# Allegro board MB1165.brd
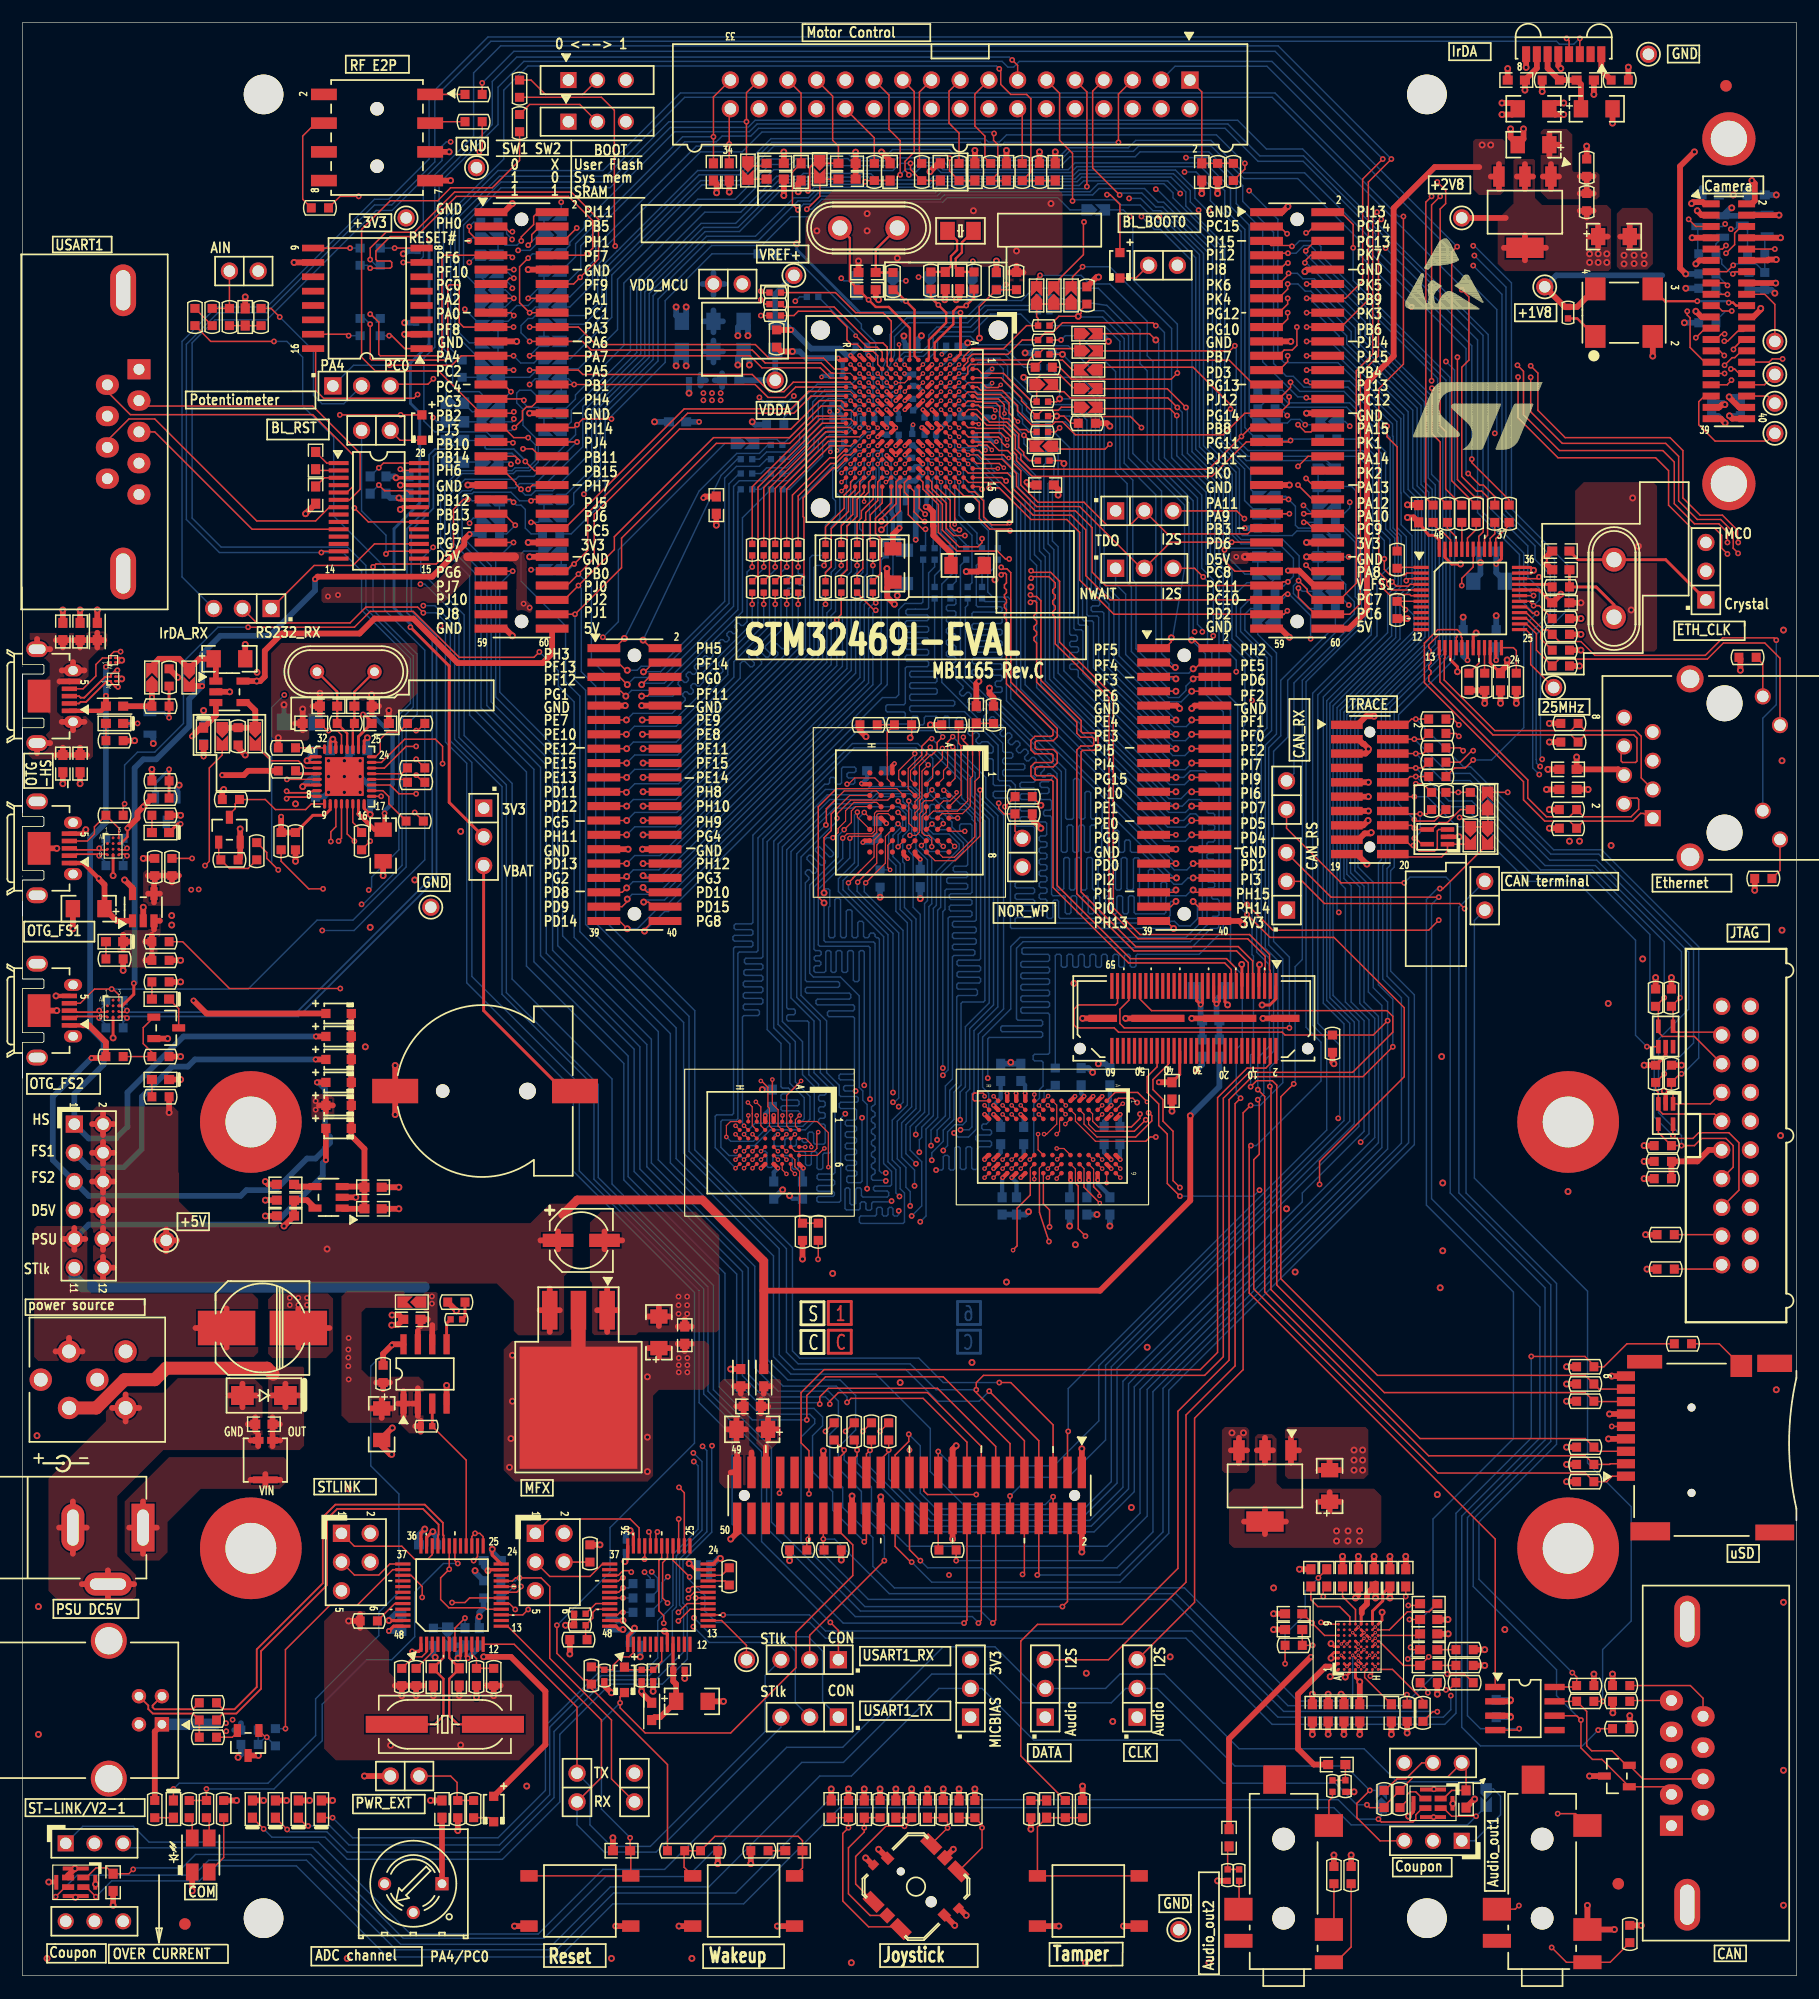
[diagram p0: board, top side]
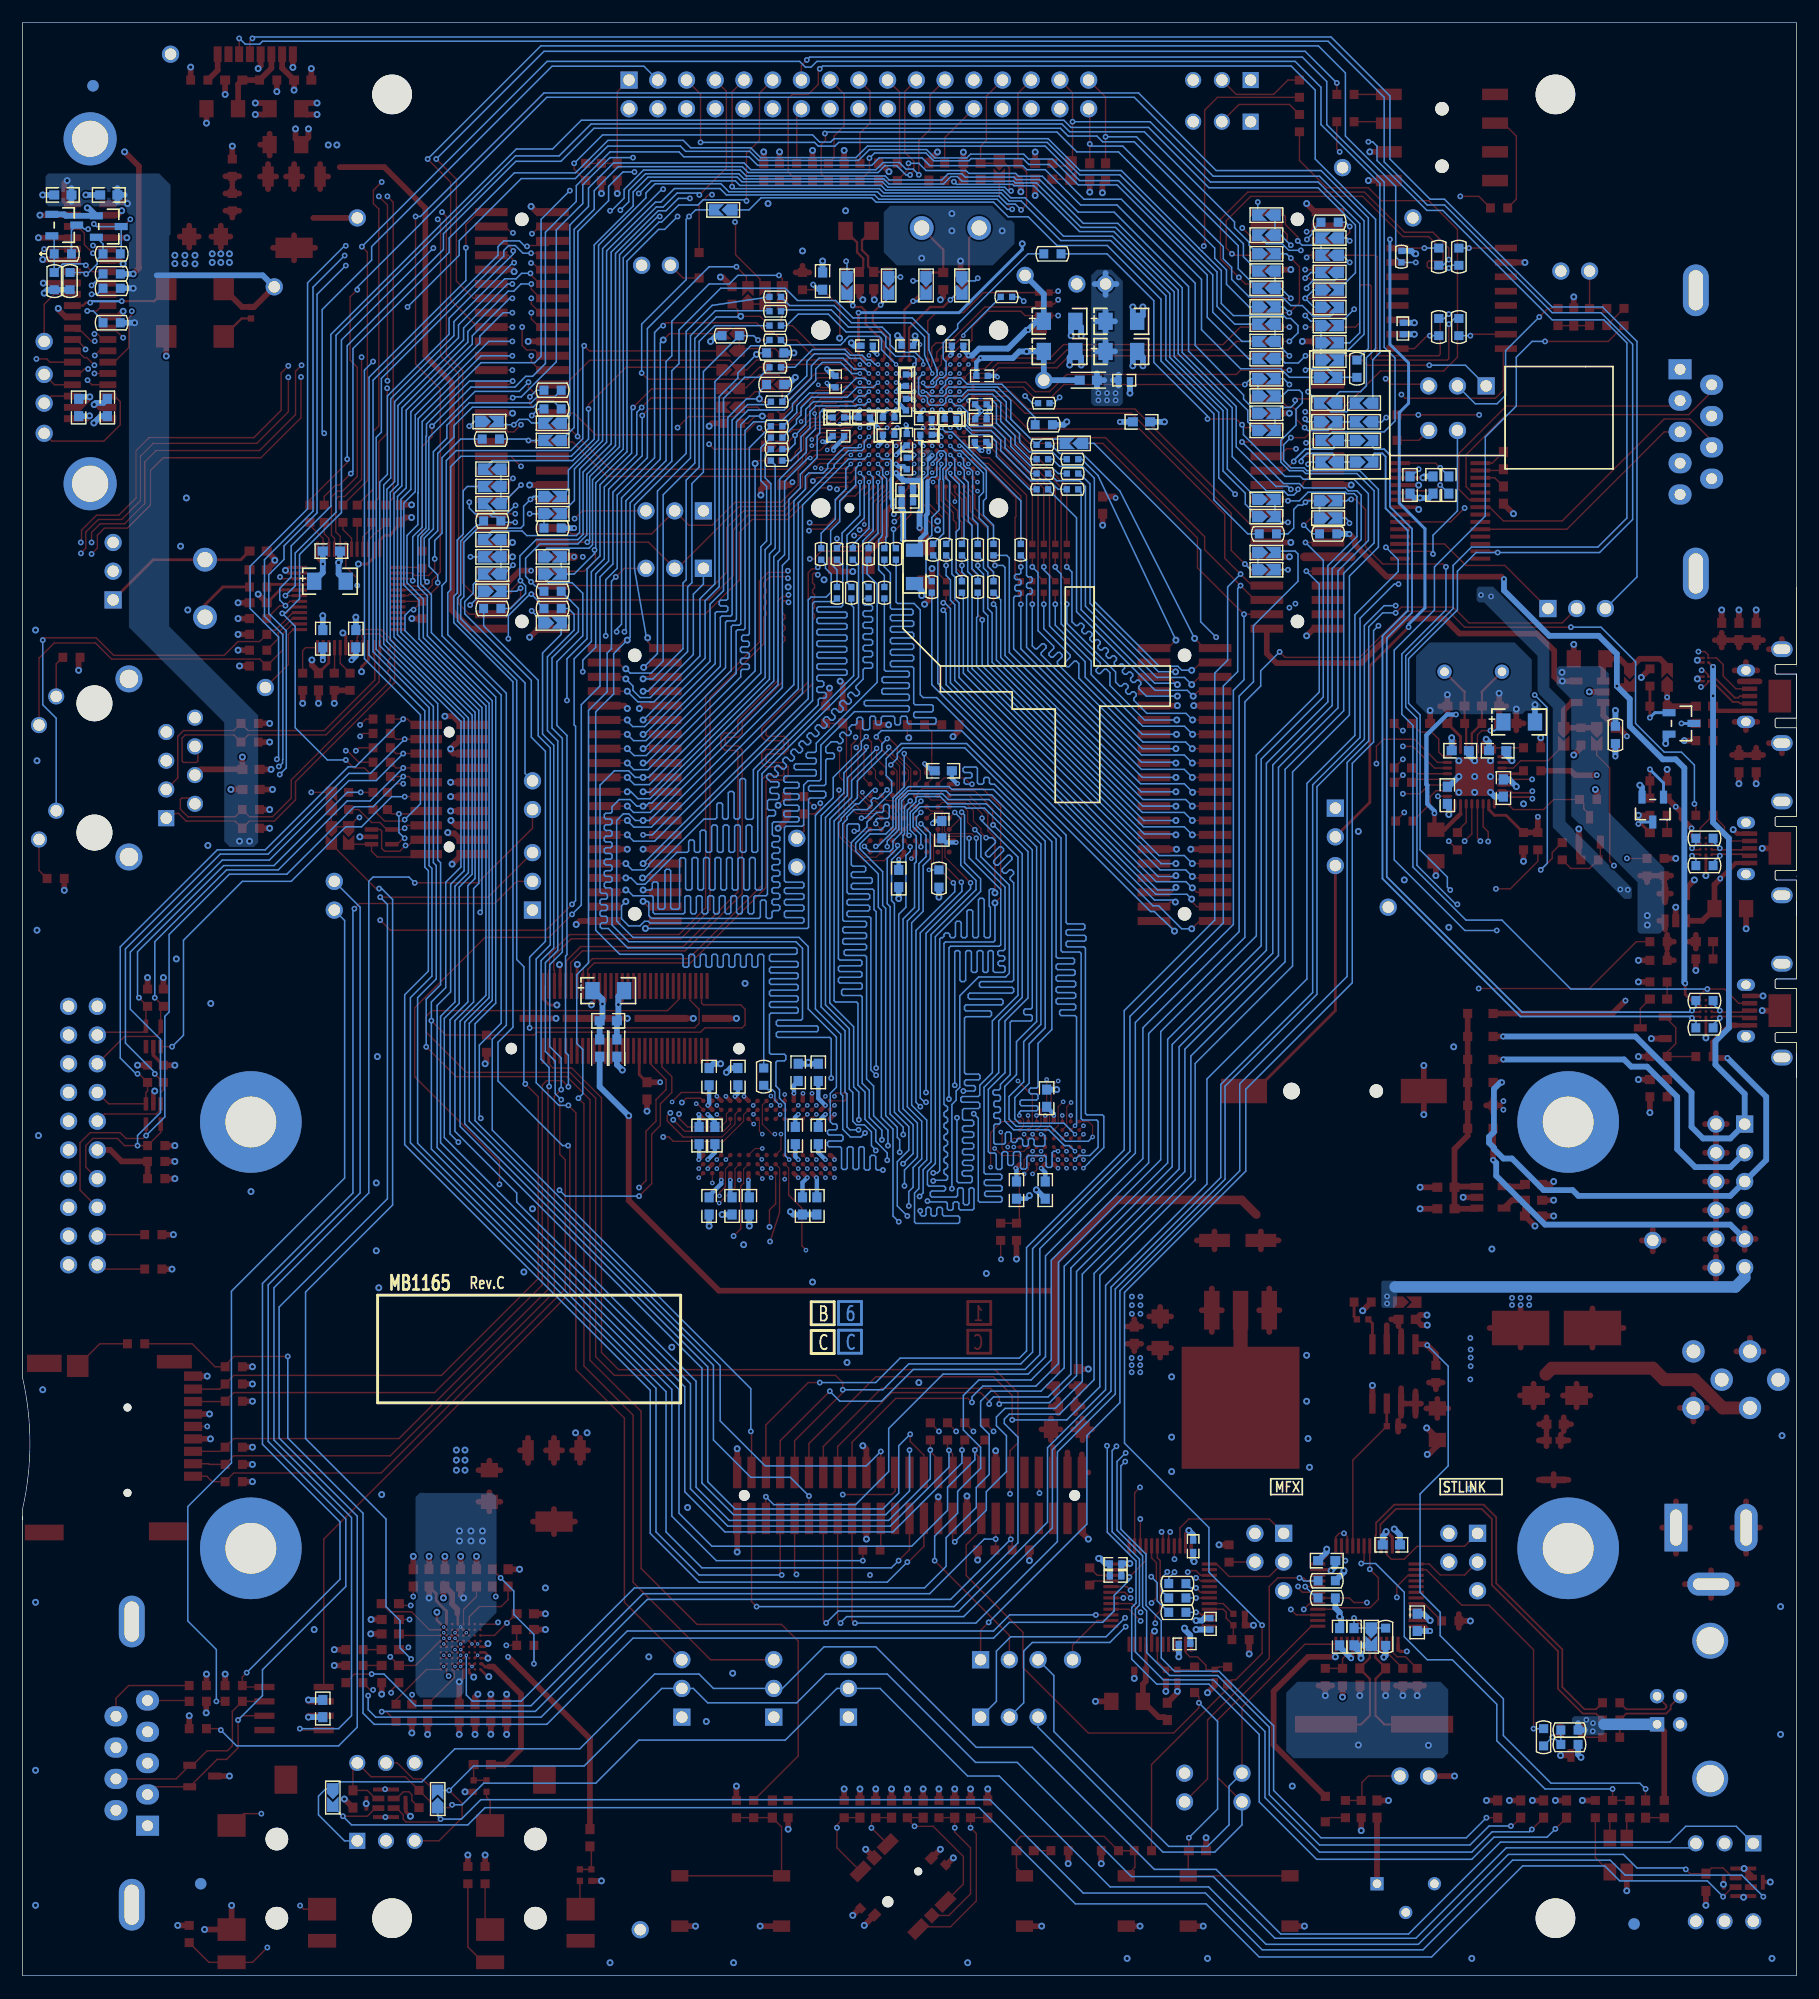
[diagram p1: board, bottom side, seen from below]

Outline 156.84 x 172.72 mm; copper layers: TOP, L2_GND, L3_SIG, L4_VCC, L5_GND, BOTTOM. Coordinates in mm from the lower left corner of the outline.
Outline path: 0,115.82 0,115.8 ; 0,115.14 0,102.87 ; 0,97.26 0,97.21 ; 0,172.72 156.84,172.72 156.84,52.86 arc(156.2,47.08) 156.84,41.3 156.84,40.28 156.84,40.59 156.84,0 0,0 0,81.53 0,79.38 0,82.54 1.79,82.54 1.89,82.64 1.89,83.29 1.79,83.39 0,83.39 0,87.29 1.79,87.29 1.89,87.39 1.89,88.04 1.79,88.14 0,88.14 0,95 0,93.73 0,96.89 1.79,96.89 1.89,96.99 1.89,97.64 1.79,97.75 0,97.75 0,101.64 1.79,101.64 1.89,101.75 1.89,102.4 1.79,102.5 0,102.5 0,109.35 0,107.19 0,110.36 1.79,110.36 1.89,110.46 1.89,111.11 1.79,111.21 0,111.21 0,115.11 1.79,115.11 1.89,115.21 1.89,115.86 1.79,115.96 0,115.96 0,172.72

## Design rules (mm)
net group +2V8: nets I2C1_SCL_C I2C1_SDA_C
net group +3V3_ST_LINK: nets NETLD12_4 STM_RST
net group A0: nets A0 NETR236_1
net group A1: nets A1 NETR232_1
net group A2: nets A2 NETR230_1
net group A3: nets A3 NETR226_1
net group A4: nets A4 NETR223_1
net group A5: nets A5 NETR221_1
net group A6: nets A6 NETR248_1
net group A7: nets A7 NETR245_1
net group A8: nets A8 NETR249_1
net group A9: nets A9 NETR261_1
net group A10: nets A10 NETR251_1
net group A11: nets A11 NETR250_1
net group A12: nets A12 NETR269_1
net group A13: nets A13 NETR257_1
net group A14: nets A14 NETR270_1
net group A15: nets A15 NETR259_1
net group A16: nets A16 NETR260_2
net group A17: nets A17 NETR271_1
net group A18: nets A18 NETR258_1
net group BOOT0: nets BOOT0 NETR3_2
net group D0: nets D0 NETR268_1
net group D1: nets D1 NETR256_1
net group D2: nets D2 NETR262_1
net group D3: nets D3 NETR273_1
net group D4: nets D4 NETR58_1
net group D5: nets D5 NETR50_1
net group D6: nets D6 NETR49_1
net group D7: nets D7 NETR59_1
net group D8: nets D8 NETR51_1
net group D9: nets D9 NETR60_1
net group D10: nets D10 NETR62_1
net group D11: nets D11 NETR52_1
net group D12: nets D12 NETR61_1
net group D13: nets D13 NETR56_1
net group D14: nets D14 NETR65_1
net group D15: nets D15 NETR66_1
net group D16: nets D16 NETR53_2
net group D17: nets D17 NETR54_2
net group D18: nets D18 NETR63_2
net group D19: nets D19 NETR64_2
net group D20: nets D20 NETR55_2
net group D21: nets D21 NETR266_2
net group D22: nets D22 NETR276_2
net group D23: nets D23 NETR275_2
net group D24: nets D24 NETR265_2
net group D25: nets D25 NETR264_2
net group D26: nets D26 NETR263_2
net group D27: nets D27 NETR274_2
net group D28: nets D28 NETR247_2
net group D29: nets D29 NETR240_2
net group D30: nets D30 NETR241_2
net group D31: nets D31 NETR244_2
net group DIFFPAIR1: nets NETCN9_2 NETCN9_3
net group LCD_B4: nets LCD_B4 NETLD1_2
net group LCD_B5: nets LCD_B5 NETLD2_2
net group LCD_B6: nets LCD_B6 NETLD3_2
net group LCD_B7: nets LCD_B7 NETLD4_2
net group MIC_CLK: nets MIC_CLK NETSB25_2
net group MIC_DATA: nets MIC_DATA NETSB26_1
net group NETC11_1: nets NETC11_1 NETCN1_26
net group NETC12_2: nets NETC12_2 NETCN1_19
net group NETC13_2: nets NETC13_2 NETCN1_17
net group NETC14_2: nets NETC14_2 NETCN1_15
net group NETC15_1: nets NETC15_1 NETCN1_14
net group NETC16_2: nets NETC16_2 PA6
net group NETC20_1: nets NETC20_1 PH0
net group NETC21_1: nets NETC21_1 PC15
net group NETC22_1: nets NETC22_1 PC14
net group NETC25_1: nets NETC25_1 NETC25_2
net group NETC33_2: nets NETC33_2 NETR67_1
net group NETC39_1: nets NETC39_1 NETC40_1
net group NETC75_1: nets NETC75_1 NETC75_2
net group NETC80_1: nets NETC80_1 NETC80_2
net group NETC81_1: nets NETC81_1 NETC81_2
net group NETC139_1: nets NETC139_1 NETC139_2
net group NETC155_1: nets NETC155_1 NETC155_2
net group NETCN4_31: nets NETCN4_31 PA4
net group NETCN12_2: nets NETCN12_2 PA13
net group NETCN12_4: nets NETCN12_4 PA14
net group NETCN12_8: nets NETCN12_8 PA15
net group NETCN13_2: nets NETCN13_2 PA11
net group NETCN13_4: nets NETCN13_4 PA10
net group NETCN17_2: nets NETCN17_2 PAR_D4
net group NETCN17_3: nets NETCN17_3 PAR_D11
net group NETCN17_7: nets NETCN17_7 PAR_D2
net group NETCN17_8: nets NETCN17_8 PAR_D3
net group NETCN17_10: nets NETCN17_10 NETR142_1
net group NETCN18_22: nets NETCN18_22 PK7
net group NETCN22_3: nets NETCN22_3 NETR182_2
net group NETCN23_7: nets NETCN23_7 NETJP13_1
net group NETD15_2: nets NETD15_2 NETJP20_2
net group NETJP7_3: nets NETJP7_3 PA8
net group NETJP18_3: nets NETJP18_3 PAR_D1
net group NETLD6_2: nets NETLD6_2 NETR111_1
net group NETR6_1: nets NETR6_1 PB2
net group NETR40_1: nets NETR40_1 PB6
net group NETR41_1: nets NETR41_1 PG15
net group NETR42_1: nets NETR42_1 PH7
net group NETR48_1: nets NETR48_1 PF11
net group NETR69_1: nets NETR69_1 PA2
net group NETR82_1: nets NETR82_1 PA3
net group NETR84_1: nets NETR84_1 PD7
net group NETR88_2: nets NETR88_2 NETSB16_1
net group NETR94_1: nets NETR94_1 PB10
net group NETR98_1: nets NETR98_1 PB11
net group NETR99_1: nets NETR99_1 PD5
net group NETR113_1: nets NETR113_1 PA5
net group NETR134_1: nets NETR134_1 PG9
net group NETR140_1: nets NETR140_1 NETR140_2
net group NETR214_2: nets NETR214_2 PI14
net group NETR222_1: nets NETR222_1 PF10
net group NETR233_2: nets NETR233_2 PC2
net group NETR235_2: nets NETR235_2 PG14
net group NETR242_2: nets NETR242_2 PG11
net group NETR243_2: nets NETR243_2 PH3
net group NETR246_2: nets NETR246_2 PH5
net group NETR267_1: nets NETR267_1 PG8
net group NETR285_1: nets NETR285_1 PH2
net group NETR290_2: nets NETR290_2 PI8
net group NETSB31_2: nets NETSB31_2 PC1
net group NETSB32_2: nets NETSB32_2 PI11
net group NETSB34_2: nets NETSB34_2 PC0
net group NETSB56_2: nets NETSB56_2 PH4
net group PB0: nets PB0 ULPI_D1
net group PB1: nets PB1 ULPI_D2
net group PB5: nets PB5 ULPI_D7
net group VDDA: nets VDDA VREF+
net group +1V8: nets NETR26_1
net group +5V: nets NETLD10_1
net group A19: nets A19 NETCN12_6 NETCN12_14 NETR37_1 NETSB9_1 T_JTDO
net group A20: nets A20 NETCN12_16 NETCN16_3 NETR35_1 NETSB7_1 PB4
net group A21: nets A21 NETCN12_18 NETR32_1 NETSB5_1 PAR_D6
net group A22: nets A22 NETCN12_20 NETR34_1 NETSB19_1 PAR_D7
net group A23: nets A23 NETCN12_12 NETR38_1 NETR238_1
net group DATA: nets NETR289_2 PE0 PE1 PI4 PI5
net group LCD_R0: nets LCD_R0 MII_TXD0 NETR254_1 PB12 PG13 ULPI_D5
net group LED_STLINK: nets LED_STLINK NETLD12_2 NETLD12_3
net group MIC_VDD: nets MIC_VDD NETCN25_5 NETR186_1
net group NETB2_2: nets NETB2_2 NETR163_1 NETR163_2 PA0
net group NETB3_2: nets NETB3_2 NETC100_1 PC13
net group NETC24_2: nets NETC24_2 NETCN3_1 NETJP3_2 NETR28_1 NETR28_2
net group NETC37_1: nets NETC37_1 NETL2_1 NETR74_2 NETR95_1
net group NETC69_1: nets NETC69_1 NETC69_2 NETC78_2
net group NETC92_1: nets NETC92_1 NETC92_2 NETCN26_6
net group NETC101_1: nets NETC101_1 NETC101_2 NETCN26_4
net group NETCN2_1: nets NETCN2_1 NETR172_2 NETR288_2 PB9
net group NETCN2_3: nets NETCN2_3 NETR179_2 NETR287_2 PB8
net group NETCN12_10: nets NETCN5_5 NETCN12_10 NETR114_1 RESET#
net group NETCN13_3: nets NETCN13_3 NETD5_C3 NETSB67_1 PA12
net group NETCN14_2: nets NETCN14_2 NETD6_D3 PB14
net group NETCN14_3: nets NETCN14_3 NETD6_C3 PB15
net group NETCN17_1: nets NETCN2_4 NETCN17_1 PAR_D8
net group NETCN22_2: nets NETCN22_2
net group NETJP19_2: nets NETJP19_2 NETR97_2 PA9 VBUS_FS1
net group NETLD8_2: nets NETR119_1
net group NETLD11_1: nets NETLD11_1 NETLD11_2 NETR292_1 PWR_ENN USB_RENUMN VUSB_ST_LINK
net group NETR43_1: nets NETR43_1 NETR43_2 PH6
net group NETR44_1: nets NETR44_1 NETR44_2 PC5
net group NETR45_1: nets NETR45_1 NETR45_2 PC4
net group NETR46_1: nets NETR46_1 NETR46_2 PA7
net group NETR47_1: nets NETR47_1 NETR47_2 PA1
net group NETR57_1: nets NETR57_1 NETR57_2 PC3
net group NETR109_1: nets NETR109_1 NETR126_2 PB13 VBUS_FS2
net group NETR116_2: nets NETR117_2
net group NETR216_1: nets NETR27_1 NETR216_1 PF9
net group NETR217_2: nets NETR23_1 NETR217_2 PF7
net group NETR227_1: nets NETR25_1 NETR227_1 PF6
net group NETR228_2: nets NETR228_2 NETR237_1 PF8

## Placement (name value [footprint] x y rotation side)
B1  TD-0341 [RESET_Black]  [PB10]  49.28 6.6 0 top
B2  WKUP  [PB10]  63.75 6.6 0 top
B3  USER (Blue)  [PB10]  94.23 6.6 0 top
B4  EVQQ7  [SW-JOY]  78.99 7.87 45 top
BT1  CR1220 holder  [BAT_2SM_CR1220]  40.89 78.23 180 top
C1  100nF  [0603C]  132.08 167.64 180 top
C2  100nF  [0603C]  138.18 167.64 0 top
C3  4.7uF  [TAN-A]  133.6 165.1 0 top
C4  4.7uF  [TAN-A]  139.19 165.1 180 top
C5  10uF  [TAN-A]  133.6 161.93 0 top
C6  [N_A]  [0603C]  66.55 160.27 180 top
C7  [N_A]  [0603C]  72.9 160.27 180 top
C8  [N_A]  [0603C]  61.09 159.51 90 top
C9  [N_A]  [0603C]  62.48 159.51 90 top
C10  [N_A]  [0603C]  68.83 159.51 90 top
C11  100nF  [0603C]  76.71 159.51 90 top
C12  [N_A]  [0603C]  81.15 159.51 270 top
C13  [N_A]  [0603C]  84.2 159.51 270 top
C14  [N_A]  [0603C]  87 159.51 270 top
C15  100nF  [0603C]  91.31 159.51 90 top
C16  1nF  [0603C]  104.27 159.51 90 top
C17  10nF  [0603C]  66.55 158.88 0 top
C18  [N_A]  [0603C]  72.9 158.88 180 top
C19  10uF  [TAN-A]  140.72 153.8 180 top
C20  20pF  [0603C]  74.68 150.62 180 top
C21  1.5pF  [0603C]  81.58 149.91 270 top
C22  1.5pF  [0603C]  82.85 149.91 270 top
C23  20pF  [0603C]  74.68 149.1 0 top
C24  [N_A]  [0603C]  19.68 146.69 270 top
C25  100nF  [0603C]  25.91 133.99 270 top
C26  [N_A]  [0603C]  90.42 131.83 180 top
C27  100nF  [0603C]  25.91 130.94 90 top
C28  [N_A]  [0603C]  61.34 130.05 90 top
C29  100nF  [0603C]  123.44 129.29 90 top
C30  22pF  [0603C]  136.02 125.98 180 top
C31  2.2uF[N_A]  [1206C]  76.96 124.71 270 top
C32  2.2uF  [1206C]  83.57 124.71 0 top
C33  22pF  [0603C]  136.02 124.33 0 top
C34  100nF  [0603C]  136.02 121.41 180 top
C35  100nF  [0603C]  3.56 118.87 90 top
C36  100nF  [0603C]  5.08 118.87 90 top
C37  4.7uF  [TAN-A]  18.29 116.46 180 top
C38  100nF  [0603C]  130.68 114.43 90 top
C39  33pF  [0603C]  27.05 112.27 180 top
C40  33pF  [0603C]  30.1 112.27 0 top
C41  100nF  [0603C]  84.33 111.51 90 top
C42  100nF  [0603C]  25.53 110.74 180 top
C43  100nF  [0603C]  31.62 110.74 0 top
C44  100nF  [0603C]  3.56 107.19 270 top
C45  100nF  [0603C]  5.08 107.19 270 top
C46  100nF  [0603C]  136.65 106.68 0 top
C47  100nF  [0603C]  136.65 104.9 0 top
C48  4.7uF  [TAN-A]  31.88 99.95 90 top
C49  4.7uF  [TAN-A]  5.84 94.36 0 top
C52  100nF  [0603C]  101.63 78.24 270 top
C53  10nF_X7R_0603  [0603C]  23.24 69.98 0 top
C54  1uF_X5R_0603  [0603C]  30.99 69.72 180 top
C55  100nF  [0603C]  23.24 68.58 0 top
C56  100nF  [0603C]  30.99 67.82 180 top
C57  1uF_X5R_0603  [0603C]  23.24 67.18 180 top
C58  47uF  [CAE_5R3X5R3_H5R4]  49.4 65.02 0 top
C59  100nF  [0603C]  34.42 58.04 0 top
C60  220uF  [C310M-6]  21.21 57.28 180 top
C61  10uF  [TAN-A]  56.26 56.9 270 top
C62  100nF  [0603C]  58.55 56.64 90 top
C63  100nF  [0603C]  64.52 50.34 180 top
C64  100nF  [0603C]  21.34 48.77 180 top
C65  4.7uF  [TAN-A]  31.75 48.77 90 top
C66  10uF  [TAN-A]  64.52 48.31 0 top
C67  10uF  [TAN-A]  115.57 43.31 270 top
C68  4.7uF  [0603C]  113.92 35.18 270 top
C69  1uF  [0603C]  115.32 35.18 90 top
C70  4.7uF  [0603C]  116.71 35.18 90 top
C71  4.7uF  [0603C]  118.11 35.18 90 top
C72  1uF  [0603C]  119.51 35.18 90 top
C73  100nF  [0603C]  120.9 35.18 90 top
C74  1uF  [0603C]  122.3 35.18 90 top
C75  2.2uF  [0603C]  124.33 32.89 180 top
C76  4.7uF  [0603C]  112.39 32 0 top
C77  2.2uF  [0603C]  124.33 31.5 0 top
C78  4.7uF  [0603C]  112.39 30.61 0 top
C79  2.2uF  [0603C]  124.33 30.23 0 top
C80  100nF  [0603C]  124.33 28.83 0 top
C81  100nF  [0603C]  124.33 27.43 0 top
C82  100nF  [0402C]  58.04 27.05 180 top
C83  100nF[N_A]  [0402C]  55.75 26.54 90 top
C84  20pF  [0603C]  36.32 26.42 270 top
C85  20pF  [0603C]  38.61 26.42 270 top
C86  1uF  [TAN-A]  59.18 24.26 180 top
C87  100nF  [0603C]  114.05 23.24 270 top
C88  100nF  [0603C]  115.44 23.24 270 top
C89  4.7uF  [0603C]  116.84 23.24 270 top
C90  100nF  [0603C]  118.24 23.24 270 top
C91  1uF  [0603C]  121.03 23.24 270 top
C92  4.7uF  [0603C]  116.2 18.67 180 top
C93  100nF  [0603C]  127.64 15.62 270 top
C94  100nF  [0603C]  37.08 14.73 90 top
C95  10nF[N_A]  [0603C]  71.5 14.73 270 top
C96  10nF[N_A]  [0603C]  74.42 14.73 270 top
C97  10nF[N_A]  [0603C]  77.22 14.73 270 top
C98  10nF[N_A]  [0603C]  80.01 14.73 270 top
C99  10nF[N_A]  [0603C]  82.8 14.73 270 top
C100  100nF  [0603C]  90.55 14.73 270 top
C101  4.7uF  [0603C]  106.68 12.19 90 top
C102  100nF  [0603C]  52.96 11.05 0 top
C103  [N_A]  [0603C]  68.2 11.05 0 top
C104  100nF  [0603C]  8 8.26 270 top
C105  100nF  [0603C]  153.29 157.48 0 bottom
C106  100nF  [0603C]  149.22 157.48 180 bottom
C107  [N_A]  [0603C]  86.11 149.86 270 bottom
C108  1uF  [TAN-A]  65.15 146.3 0 bottom
C109  4.7uF  [TAN-A]  59.69 146.3 0 bottom
C110  100nF  [0402C]  34.8 145.67 90 bottom
C111  100nF  [0402C]  82.17 144.15 0 bottom
C112  100nF  [0402C]  78.61 144.15 0 bottom
C113  100nF  [0402C]  74.17 144.15 180 bottom
C114  1uF  [TAN-A]  65.15 143.64 0 bottom
C115  4.7uF  [TAN-A]  59.69 143.64 0 bottom
C116  100nF  [0402C]  72.01 141.48 0 bottom
C117  100nF  [0402C]  78.74 141.1 90 bottom
C118  100nF  [0402C]  59.44 141.1 180 bottom
C119  100nF  [0402C]  84.96 140.97 90 bottom
C120  100nF  [0402C]  72.11 138.96 180 bottom
C121  100nF  [0402C]  78.74 138.94 270 bottom
C122  100nF  [0603C]  151.89 138.68 90 bottom
C123  100nF  [0603C]  149.35 138.68 90 bottom
C124  100nF  [0402C]  84.71 137.79 180 bottom
C125  100nF  [0402C]  82.42 137.79 0 bottom
C126  100nF  [0402C]  80.26 137.79 180 bottom
C127  100nF  [0402C]  76.96 137.67 0 bottom
C128  100nF  [0402C]  74.8 137.67 180 bottom
C129  100nF  [0402C]  72.11 137.64 180 bottom
C130  [N_A]  [0603C]  57.91 137.41 0 bottom
C131  100nF  [0402C]  80.26 136.27 180 bottom
C132  100nF  [0402C]  76.96 136.27 0 bottom
C133  100nF  [0402C]  84.71 136.14 180 bottom
C134  100nF  [0402C]  78.66 135.84 90 bottom
C135  100nF  [0402C]  72.14 135.64 180 bottom
C136  100nF  [0402C]  78.66 133.73 270 bottom
C137  100nF  [0603C]  34.16 131.83 90 bottom
C138  100nF  [0603C]  32.13 131.83 270 bottom
C139  100nF  [0603C]  30.73 131.83 90 bottom
C140  2.2uF  [0402C]  78.61 131.44 0 bottom
C141  100nF  [0402C]  78.61 130.3 0 bottom
C142  100nF  [0603C]  129.54 125.98 0 bottom
C143  2.2uF  [1206C]  77.98 124.59 270 bottom
C144  10uF  [TAN-A]  129.67 123.32 0 bottom
C145  100nF  [0603C]  130.3 118.24 90 bottom
C146  100nF  [0603C]  127.38 118.24 270 bottom
C147  4.7uF  [TAN-A]  24.51 110.87 0 bottom
C148  100nF  [0603C]  29.72 108.33 180 bottom
C149  100nF  [0603C]  26.42 108.33 180 bottom
C150  100nF  [0603C]  75.44 106.55 180 bottom
C151  100nF  [0603C]  25.91 105.03 270 bottom
C152  100nF  [0603C]  30.86 104.39 90 bottom
C153  100nF  [0603C]  75.56 101.35 270 bottom
C154  100nF  [0603C]  79.38 97.03 270 bottom
C155  10uF  [TAN-A]  105.06 87.11 0 bottom
C156  100nF  [0603C]  105.06 84.44 180 bottom
C157  100nF  [0603C]  88.27 79.88 90 bottom
C158  100nF  [0603C]  86.49 79.88 90 bottom
C159  100nF  [0603C]  96.14 79.5 90 bottom
C160  100nF  [0603C]  93.6 79.5 90 bottom
C161  100nF  [0603C]  66.29 77.6 90 bottom
C162  100nF  [0603C]  97.03 74.3 90 bottom
C163  100nF  [0603C]  95.63 74.3 90 bottom
C164  100nF  [0603C]  88.52 74.3 90 bottom
C165  100nF  [0603C]  86.49 74.3 90 bottom
C166  100nF  [0603C]  68.96 69.47 270 bottom
C167  100nF  [0603C]  66.42 69.47 270 bottom
C168  100nF  [0603C]  96.14 68.07 270 bottom
C169  100nF  [0603C]  94.11 68.07 270 bottom
C170  100nF  [0603C]  92.58 68.07 270 bottom
C171  100nF  [0603C]  87.88 68.07 270 bottom
C172  100nF  [0603C]  86.61 68.07 270 bottom
C173  100nF  [0603C]  35.81 38.1 180 bottom
C174  100nF  [0402C]  53.34 37.97 270 bottom
C175  100nF  [0603C]  41.53 36.7 0 bottom
C176  100nF  [0402C]  60.2 36.45 180 bottom
C177  100nF  [0402C]  60.2 35.31 0 bottom
C178  100nF  [0603C]  33.53 31.24 270 bottom
C179  100nF  [0402C]  51.82 31.11 270 bottom
C180  100nF  [0603C]  40.39 29.97 270 bottom
C181  100nF  [0603C]  39.12 29.97 90 bottom
C182  100nF  [0402C]  54.1 29.34 180 bottom
C183  100nF  [0603C]  130.3 23.62 90 bottom
CN1  MC_connector  [IDC34S]  103.22 167.64 270 top
CN2  F206A-2_04MGF-A  [SSM-104-L-DH]  31.34 162.56 90 top
CN3  -  [SIP2]  18.29 150.75 0 top
CN4  F1000-2_20MGF-L0A  [CLM-120-02-L-D]  150.88 147.19 270 top
CN5  P1039-2_30MGF-089-1A  [FTR-130-53-L-D-LC]  44.12 137.54 270 top
CN6  P1039-2_30MGF-089-1A  [FTR-130-53-L-D-LC]  112.7 137.54 270 top
CN7  DB9-male USART1  [DB9_M]  10.29 136.53 90 top
CN8  475900001  [MOLEX_47590001]  4.14 113.16 270 top
CN9  J0011D21B  [RJ45_J0011D01BNL]  144.15 102.36 270 top
CN10  P1039-2_20MGF-089-1A  [FTR-120-53-L-D-LC]  54.1 105.33 270 top
CN11  P1039-2_20MGF-089-1A  [FTR-120-53-L-D-LC]  102.72 105.33 270 top
CN12  P127B-2_10MGF-079-1E7A  [FTSH-110-01-L-DV]  119.13 104.9 270 top
CN13  475900001  [MOLEX_47590001]  4.14 99.69 270 top
CN14  475900001  [MOLEX_47590001]  4.14 85.34 270 top
CN15  -  [QSH-030-01-F-D-A]  103.57 84.66 180 top
CN16  JTAG  [IDC20S]  150.24 85.72 0 top
CN17  PJS008-2000  [MSD_PJS008_]  147.57 42.7 90 top
CN18  P127B-2_25MGF-079-1A  [FTSH-125-01-F-DV]  78.42 42.47 180 top
CN19  DC-10B  [PWR_JACK_DC10]  10.64 39.62 0 top
CN20  [N_A]  [HDR_2X3-1_2R54-6]  28.19 39.12 270 top
CN21  [N_A]  [HDR_2X3-1_2R54-6]  45.34 39.12 270 top
CN22  USB-typeB connector  [USB-B]  12.32 22.23 270 top
CN23  DB9-male CAN connector  [DB9_M]  145.8 18.8 270 top
CN24  -  [SIP2]  49.02 15.37 90 top
CN25  Coupon Connectors  [COUPON]  124.71 15.37 90 top
CN26  PJ3028B-3  [PJ3028B]  111.51 5.08 90 top
CN27  PJ3028B-3  [PJ3028B]  134.37 5.08 90 top
CN28  Coupon Connectors  [COUPON]  6.35 8.26 270 top
D1  BAT60JFILM  [SOD-323]  97.03 151.26 270 top
D2  BAT60JFILM  [SOD-323]  35.31 136.91 270 top
D3  ESDA14V2-2BF3  [BGA4_0R4_0R8X0R8]  8 116.33 90 top
D4  USBULC6-2F3  [BGA4_0R4_1X1]  8 114.68 90 top
D5  EMIF02-USB03F2  [BGA11_0R5_1R57X2R07]  8 99.87 0 top
D6  EMIF02-USB03F2  [BGA11_0R5_1R57X2R07]  8 85.52 0 top
D7  BAT60JFILM  [SOD-323]  27.94 85.09 0 top
D8  BAT60JFILM  [SOD-323]  27.94 83.06 0 top
D9  BAT60JFILM  [SOD-323]  27.94 81.03 0 top
D10  BAT60JFILM  [SOD-323]  27.94 78.99 0 top
D11  BAT60JFILM  [SOD-323]  27.94 76.96 0 top
D12  BAT60JFILM  [SOD-323]  27.94 74.93 0 top
D13  ZEN056V130A24LS  [TYCO_ZEN056V130A24LS]  21.46 45.59 90 top
D14  ESDCAN24-2BLY  [SOT-23]  140.97 17.65 90 top
D15  BAT60JFILM  [SOD-323]  41.66 14.73 270 top
D16  BAT60JFILM  [SOD-323]  53.21 26.16 270 top
H1  POSITION HOLE  [HOLE_C9D4R5]  20.18 75.5 0 top
H2  POSITION HOLE  [HOLE_C9D4R5]  136.66 75.5 0 top
H3  POSITION HOLE  [HOLE_C9D4R5]  20.18 37.79 0 top
H4  POSITION HOLE  [HOLE_C9D4R5]  136.66 37.79 0 top
JP1  -  [SIP2]  99.57 151.26 0 top
JP2  -  [SIP2]  63.63 149.61 180 top
JP3  -  [SIP3]  27.43 140.59 0 top
JP4  -  [SIP2]  32.51 136.65 180 top
JP5  -  [SIP3]  96.65 129.54 0 top
JP6  -  [SIP3]  96.65 124.46 0 top
JP7  -  [SIP3]  148.84 121.67 90 top
JP8  -  [SIP3]  21.97 120.9 180 top
JP9  -  [SIP2]  111.76 105.66 270 top
JP10  -  [SIP3]  40.77 103.25 270 top
JP11  -  [SIP2]  88.39 98.04 90 top
JP12  -  [SIP3]  111.76 94.23 90 top
JP13  -  [SIP2]  129.29 94.23 90 top
JP14  Header 6X2  [HDR_2X6_2R54]  4.57 75.31 270 top
JP15  -  [SIP3]  72.14 27.94 180 top
JP16  -  [SIP3]  83.82 22.86 90 top
JP17  -  [SIP3]  90.42 22.86 90 top
JP18  -  [SIP3]  98.55 22.86 90 top
JP19  -  [SIP3]  72.14 22.86 180 top
JP20  -  [SIP2]  32.51 17.65 0 top
JP21  [N_A]  [SIP2]  54.1 17.91 270 top
L1  EXC-3BP121H[BEAD]  [0603L]  6.6 118.87 270 top
L2  EXC-3BP121H[BEAD]  [0603L]  8.13 112.27 180 top
L3  BEAD(FCM1608KF-601T03)  [0603L]  63.5 52.88 270 top
L4  BEAD(FCM1608KF-601T03)  [0603L]  65.53 52.88 270 top
L5  BNX002-01  [BNX001]  6.6 52.7 180 top
L6  Ferrite  [0603L]  55.63 23.37 270 top
L7  BEAD(FCM1608KF-601T03)  [0603L]  62.61 141.1 0 bottom
L8  BEAD(FCM1608KF-601T03)  [0603L]  105.82 82.03 90 bottom
L9  BEAD(FCM1608KF-601T03)  [0603L]  104.3 82.03 90 bottom
LD1  Green  [0603D]  26.42 14.73 270 top
LD2  Orange  [0603D]  24.38 14.73 270 top
LD3  Red  [0603D]  22.35 14.73 270 top
LD4  Blue  [0603D]  20.32 14.73 270 top
LD5  Green  [0603D]  8.13 110.74 0 top
LD6  Red  [0603D]  16 109.6 90 top
LD7  Green  [0603D]  12.19 101.09 0 top
LD8  Red  [0603D]  8.13 91.44 0 top
LD9  Green  [0603D]  12.19 86.36 0 top
LD10  red  [0603D]  12.19 79.25 0 top
LD11  Red  [0603D]  13.34 14.73 90 top
LD12  HSMF-A201-A00J1  [LED2_3528]  15.75 10.67 0 top
NOREF  -  [unnamed]  124.18 166.37 0 top
NOREF#2  -  [#2]  0 0 0 top
NOREF#3  -  [#2]  13.59 -41.66 0 top
NOREF#4  -  [unnamed]  14.35 4.57 0 top
NOREF#5  -  [unnamed]  124.18 5.08 0 top
NOREF#6  -  [#2]  322.2 176.15 0 top
NOREF#7  -  [#2]  72 55.3 0 top
NOREF#8  -  [unnamed]  21.31 166.37 0 top
NOREF#9  -  [#2]  0 0 0 top
NOREF#10  -  [#2]  450.6 -120.4 0 top
NOREF#11  -  [#2]  0 0 90 top
NOREF#12  -  [#2]  12.32 228.5 0 top
NOREF#13  -  [unnamed]  21.31 5.08 0 top
NOREF#14  -  [unnamed]  141.1 8.13 0 top
NOREF#15  -  [unnamed]  150.62 167.13 0 top
NOREF#16  -  [#2]  72 57.84 0 top
NOREF#17  -  [#2]  283.59 103.69 0 top
NOREF#18  -  [unnamed]  14.35 4.57 180 bottom
NOREF#19  -  [unnamed]  150.62 167.13 180 bottom
NOREF#20  -  [unnamed]  141.1 8.13 180 bottom
R1  47  [0603R]  135.13 167.64 0 top
R2  5.1  [0603R]  141.22 167.64 180 top
R3  10K  [0603R]  43.94 166.88 90 top
R4  0  [0603R]  39.88 166.37 180 top
R5  0  [0603R]  39.88 163.96 180 top
R6  10K  [0603R]  43.94 163.83 270 top
R7  150  [0603R]  138.3 159.89 90 top
R8  0  [0603R]  75.31 159.51 270 top
R9  0  [0603R]  79.5 159.51 90 top
R10  0  [0603R]  82.8 159.51 90 top
R11  0  [0603R]  85.6 159.51 90 top
R12  0  [0603R]  88.39 159.51 270 top
R13  100K  [0603R]  89.92 159.51 90 top
R14  3K3  [0603R]  105.66 159.51 270 top
R15  [N_A]  [0603R]  107.06 159.51 270 top
R16  120  [0603R]  138.3 156.84 90 top
R17  0  [0603R]  26.29 156.34 0 top
R18  0  [0603R]  80.31 149.91 270 top
R19  0  [0603R]  84.12 149.91 270 top
R20  0  [0603R]  76.96 149.86 90 top
R21  10K  [0603R]  86.11 149.86 90 top
R22  [N_A]  [0603R]  87.88 149.86 90 top
R23  33  [0402R]  66.55 148.84 180 top
R24  220K  [0603R]  94.11 148.59 270 top
R25  33  [0402R]  66.55 147.83 180 top
R26  10K  [0402R]  136.65 147.07 90 top
R27  33  [0402R]  66.55 146.81 180 top
R28  0  [0603R]  15.24 146.69 270 top
R29  47  [0603R]  16.76 146.69 270 top
R30  0  [0603R]  18.29 146.69 90 top
R31  0  [0603R]  21.08 146.69 90 top
R32  33  [0402R]  90.3 145.92 0 top
R33  0  [0603R]  66.67 144.78 90 top
R34  33  [0402R]  90.3 144.65 0 top
R35  33  [0402R]  90.3 143.38 0 top
R36  33  [0603R]  90.3 142.24 0 top
R37  33  [0402R]  90.17 139.19 0 top
R38  33[N_A]  [0402R]  90.17 137.92 0 top
R39  220K  [0603R]  94.11 137.29 180 top
R40  33  [0402R]  90.17 136.53 0 top
R41  33  [0402R]  90.3 133.99 0 top
R42  33  [0603R]  124.71 129.29 90 top
R43  33  [0603R]  125.98 129.29 90 top
R44  33  [0603R]  127.25 129.29 90 top
R45  33  [0603R]  128.52 129.29 90 top
R46  33  [0603R]  130.18 129.29 90 top
R47  33  [0603R]  131.44 129.29 90 top
R48  33  [0402R]  64.52 126.11 270 top
R49  33  [0402R]  65.53 126.11 270 top
R50  33  [0402R]  66.55 126.11 270 top
R51  33  [0402R]  67.56 126.11 270 top
R52  33  [0402R]  68.58 126.11 270 top
R53  33  [0402R]  70.99 126.11 90 top
R54  33  [0402R]  72.39 126.11 90 top
R55  33  [0402R]  73.79 126.11 90 top
R56  33  [0402R]  75.18 126.11 270 top
R57  33  [0603R]  121.54 125.22 90 top
R58  33  [0402R]  64.52 122.81 270 top
R59  33  [0402R]  65.53 122.81 270 top
R60  33  [0402R]  66.55 122.81 270 top
R61  33  [0402R]  67.56 122.81 270 top
R62  33  [0402R]  68.58 122.81 270 top
R63  33  [0402R]  70.99 122.81 90 top
R64  33  [0402R]  72.39 122.81 90 top
R65  33  [0402R]  73.79 122.81 270 top
R66  33  [0402R]  75.18 122.81 270 top
R67  0  [0603R]  136.02 122.81 0 top
R68  10K  [0603R]  121.54 120.78 90 top
R69  1K5  [0603R]  136.02 120.02 0 top
R70  2K2  [0603R]  136.02 118.62 0 top
R71  2K2  [0603R]  136.02 117.22 0 top
R72  240  [0603R]  152.53 116.59 180 top
R73  2K2  [0603R]  136.02 115.82 0 top
R74  22K  [0603R]  12.95 114.81 270 top
R75  2K2  [0603R]  127.89 114.43 270 top
R76  2K2  [0603R]  129.29 114.43 270 top
R77  4.87K  [0603R]  132.08 114.43 90 top
R78  47K  [0603R]  12.19 112.27 180 top
R79  10K  [0603R]  85.85 111.51 270 top
R80  22  [0603R]  125.09 111.12 0 top
R81  1M  [0603R]  28.57 110.74 180 top
R82  0  [0603R]  34.8 110.74 0 top
R83  50  [0603R]  136.78 110.74 0 top
R84  10K  [0603R]  74.8 110.62 180 top
R85  0  [0603R]  77.85 110.62 0 top
R86  10K  [0603R]  82.04 110.62 180 top
R87  22  [0603R]  125.09 109.86 0 top
R88  10K  [0603R]  19.05 109.6 90 top
R89  330  [0603R]  8.13 109.22 0 top
R90  50  [0603R]  136.78 109.09 0 top
R91  12K[1%]  [0603R]  23.37 108.58 0 top
R92  22  [0603R]  125.09 108.58 0 top
R93  22  [0603R]  125.09 107.31 0 top
R94  0  [0603R]  34.8 106.81 0 top
R95  820  [0603R]  23.37 106.55 180 top
R96  22  [0603R]  125.09 106.05 0 top
R97  22K  [0603R]  12.19 105.66 0 top
R98  0  [0603R]  34.8 105.54 0 top
R99  0  [0603R]  88.52 104.27 0 top
R100  47K  [0603R]  12.19 104.14 0 top
R101  4K7  [0603R]  18.41 104.01 0 top
R102  [N_A]  [0603R]  124.59 103.89 90 top
R103  22  [0603R]  125.86 103.89 270 top
R104  [N_A]  [0603R]  128.02 103.89 90 top
R105  50  [0603R]  136.65 103.12 0 top
R106  10K  [0603R]  88.52 102.74 0 top
R107  0  [0603R]  8.13 102.62 0 top
R108  330  [0603R]  12.19 102.62 0 top
R109  0  [0603R]  34.67 102.11 0 top
R110  50  [0603R]  136.65 101.47 0 top
R111  0  [0603R]  22.86 100.33 90 top
R112  3K3  [0603R]  24.13 100.33 90 top
R113  33  [0603R]  29.97 100.33 270 top
R114  1K  [0603R]  20.7 99.44 90 top
R115  4K7  [0603R]  18.29 98.68 180 top
R116  10K  [0603R]  11.68 98.04 270 top
R117  0  [0603R]  13.21 98.04 90 top
R118  240  [0603R]  153.92 97.03 180 top
R119  0  [0603R]  12.19 91.44 180 top
R120  620  [0603R]  8.13 89.92 0 top
R121  47K  [0603R]  12.19 89.79 180 top
R122  330  [0603R]  12.19 87.88 0 top
R123  [N_A]  [0603R]  144.4 86.49 90 top
R124  [N_A]  [0603R]  145.8 86.49 90 top
R125  10K  [0603R]  115.82 82.42 270 top
R126  47K  [0603R]  8.13 81.28 0 top
R127  22K  [0603R]  12.19 81.28 180 top
R128  [N_A]  [0603R]  144.4 79.76 270 top
R129  [N_A]  [0603R]  145.8 79.76 90 top
R130  820  [0603R]  12.19 77.72 0 top
R131  [N_A]  [0603R]  145.03 73.41 180 top
R132  [N_A]  [0603R]  145.03 72.01 180 top
R133  10K  [0603R]  145.03 70.48 0 top
R134  10K  [0603R]  68.96 65.79 270 top
R135  0  [0603R]  70.36 65.79 270 top
R136  10K  [0603R]  145.29 65.53 0 top
R137  10K  [0603R]  145.29 62.48 0 top
R140  2K2  [0402R]  38.35 58.04 180 top
R141  0  [0603R]  38.35 59.56 0 top
R142  0  [0603R]  146.81 55.88 0 top
R143  10K[N_A]  [0603R]  138.18 53.85 180 top
R144  100K  [0603R]  31.88 53.21 90 top
R145  47K  [0603R]  138.18 52.32 0 top
R146  47K  [0603R]  138.18 50.8 0 top
R147  10K  [0402R]  35.71 48.59 0 top
R148  47K  [0603R]  138.18 46.74 0 top
R149  47K  [0603R]  138.18 45.21 0 top
R150  47K  [0603R]  138.18 43.69 0 top
R151  1K5  [0603R]  68.58 37.64 0 top
R152  1K5  [0603R]  71.63 37.64 180 top
R153  0  [0603R]  81.79 37.64 0 top
R154  0  [0603R]  50.16 37.34 270 top
R155  [N_A]  [0603R]  62.48 35.31 90 top
R156  510  [0402R]  49.28 32 180 top
R157  100K  [0603R]  30.61 31.37 0 top
R158  10K  [0402R]  49.28 30.99 180 top
R159  [N_A]  [0603R]  49.15 29.72 180 top
R160  2K2  [0603R]  112.39 29.21 0 top
R161  20  [0603R]  127.51 28.83 0 top
R162  20  [0603R]  127.51 27.43 0 top
R163  0  [0603R]  50.29 26.54 270 top
R164  47K[N_A]  [0402R]  51.44 26.54 90 top
R165  10K[N_A]  [0402R]  54.74 26.54 270 top
R167  10K  [0603R]  33.53 26.42 90 top
R168  [N_A]  [0603R]  34.8 26.42 90 top
R169  4K7  [0603R]  40.13 26.42 90 top
R170  4K7  [0603R]  41.66 26.42 90 top
R171  4K7  [0603R]  124.33 25.91 0 top
R172  0  [0603R]  127.51 25.91 180 top
R173  10K  [0603R]  138.18 25.65 0 top
R174  [N_A]  [0603R]  141.35 25.65 0 top
R175  120  [0603R]  138.18 24.26 0 top
R176  0  [0603R]  141.35 24.26 0 top
R177  0  [0603R]  16.38 24.13 0 top
R178  [N_A]  [0603R]  122.43 23.24 90 top
R179  0  [0603R]  123.83 23.24 90 top
R180  0  [0603R]  16.38 22.61 0 top
R181  0  [0603R]  141.35 21.84 0 top
R182  1K5  [0603R]  16.38 21.08 0 top
R183  180  [0402R]  115.82 16.76 270 top
R184  1K  [0402R]  116.97 16.76 270 top
R185  10K  [0603R]  120.4 15.62 270 top
R186  10K  [0603R]  121.79 15.62 90 top
R187  1K  [0603R]  11.68 14.73 270 top
R188  100  [0603R]  14.73 14.73 270 top
R189  100  [0603R]  16.26 14.73 270 top
R190  0  [0603R]  17.78 14.73 90 top
R191  680  [0603R]  71.75 48.13 90 top
R192  680  [0603R]  73.53 48.13 90 top
R193  680  [0603R]  75.06 48.13 90 top
R194  510  [0603R]  76.58 48.13 90 top
R195  4K7  [0603R]  38.48 14.73 270 top
R196  2K7  [0603R]  39.88 14.73 90 top
R197  10K[N_A]  [0603R]  73.03 14.73 270 top
R198  10K[N_A]  [0603R]  75.82 14.73 270 top
R199  10K[N_A]  [0603R]  78.61 14.73 270 top
R200  10K[N_A]  [0603R]  81.41 14.73 270 top
R201  10K[N_A]  [0603R]  84.2 14.73 270 top
R202  100  [0603R]  89.15 14.73 90 top
R203  0  [0603R]  92.2 14.73 90 top
R204  4K7  [0603R]  93.73 14.73 90 top
R205  330  [0603R]  57.78 11.05 180 top
R206  220K  [0603R]  60.71 11.05 0 top
R207  100  [0603R]  65.15 11.05 0 top
R208  1K  [0402R]  106.55 8.89 90 top
R209  180  [0402R]  107.57 8.89 90 top
R210  0  [0603R]  115.95 8.89 90 top
R211  0  [0603R]  117.47 8.89 90 top
R212  [N_A]  [0603R]  142.11 3.68 270 top
R213  820  [0603R]  41.27 155.07 180 bottom
R214  0  [0603R]  65.79 152.27 0 bottom
R215  10K  [0402R]  34.92 152.02 270 bottom
R216  33  [0603R]  31.62 152.02 270 bottom
R217  33  [0603R]  29.84 152.02 90 bottom
R218  10K  [0603R]  148.97 150.5 0 bottom
R219  4K7  [0603R]  154.05 149.86 270 bottom
R220  [N_A]  [0603R]  148.97 149.22 180 bottom
R221  33  [0402R]  90.3 148.46 0 bottom
R222  33  [0402R]  69.85 148.46 180 bottom
R223  33  [0402R]  90.3 147.19 0 bottom
R224  4K7  [0603R]  152.65 149.86 270 bottom
R225  [N_A]  [0603R]  148.97 146.18 180 bottom
R226  33  [0402R]  90.3 145.92 0 bottom
R227  33  [0603R]  31.62 145.8 90 bottom
R228  33  [0603R]  29.84 145.8 270 bottom
R229  220K  [0603R]  94.23 145.03 180 bottom
R230  33  [0402R]  90.3 144.65 0 bottom
R231  220K  [0603R]  90.3 143.51 0 bottom
R232  33  [0402R]  90.3 142.24 0 bottom
R233  33  [0603R]  38.86 142.11 90 bottom
R234  220K  [0603R]  90.3 140.72 0 bottom
R235  33  [0603R]  109.98 140.21 180 bottom
R236  33  [0402R]  90.17 139.19 0 bottom
R237  33  [0402R]  66.55 139.06 180 bottom
R238  33  [0603R]  109.98 138.56 0 bottom
R239  10K  [0603R]  66.55 137.16 0 bottom
R240  33  [0402R]  90.17 137.03 180 bottom
R241  33  [0402R]  90.17 136.02 180 bottom
R242  33  [0603R]  115.44 135.89 0 bottom
R243  33  [0402R]  66.67 135.38 0 bottom
R244  33  [0402R]  90.17 135 180 bottom
R245  33  [0402R]  66.67 134.11 180 bottom
R246  33  [0402R]  64.01 134.11 0 bottom
R247  33  [0402R]  90.17 133.99 180 bottom
R248  33  [0402R]  66.67 132.84 180 bottom
R249  33  [0402R]  64.01 132.84 180 bottom
R250  33  [0402R]  66.67 131.44 180 bottom
R251  33  [0402R]  64.01 131.44 180 bottom
R252  0  [0603R]  115.32 128.65 180 bottom
R253  10K  [0603R]  109.98 128.02 180 bottom
R254  33[N_A]  [0603R]  46.74 127.51 180 bottom
R255  [N_A]  [0603R]  41.4 127.51 0 bottom
R256  33  [0402R]  76.33 126.11 270 bottom
R257  33  [0402R]  75.18 126.11 270 bottom
R258  33  [0402R]  73.79 126.11 270 bottom
R259  33  [0402R]  72.39 126.11 270 bottom
R260  33  [0402R]  70.99 126.11 90 bottom
R261  33  [0402R]  68.58 126.11 270 bottom
R262  33  [0402R]  86.23 125.73 270 bottom
R263  33  [0402R]  84.84 125.73 90 bottom
R264  33  [0402R]  83.44 125.73 90 bottom
R265  33  [0402R]  82.04 125.73 90 bottom
R266  33  [0402R]  80.64 125.73 90 bottom
R267  33  [0402R]  79.63 125.73 270 bottom
R268  33  [0402R]  76.45 122.81 270 bottom
R269  33  [0402R]  73.79 122.81 270 bottom
R270  33  [0402R]  72.39 122.81 270 bottom
R271  33  [0402R]  70.99 122.81 270 bottom
R272  0  [0603R]  109.98 122.43 0 bottom
R273  33  [0402R]  84.84 122.3 270 bottom
R274  33  [0402R]  83.57 122.3 90 bottom
R275  33  [0402R]  82.04 122.3 90 bottom
R276  33  [0402R]  80.64 122.3 90 bottom
R277  33  [0603R]  115.32 120.9 0 bottom
R278  0  [0603R]  109.98 120.9 0 bottom
R279  620  [0603R]  16 109.73 90 bottom
R280  0  [0603R]  8.13 100.58 0 bottom
R281  0  [0603R]  8.13 98.17 0 bottom
R282  10K  [0603R]  75.82 97.03 270 bottom
R283  22  [0603R]  8.13 86.23 0 bottom
R284  22  [0603R]  8.13 83.82 0 bottom
R285  0  [0603R]  91.31 79.5 90 bottom
R286  [N_A]  [0603R]  41.53 34.92 0 bottom
R287  0  [0603R]  54.74 34.67 180 bottom
R288  0  [0603R]  54.74 33.4 180 bottom
R289  100K  [0603R]  41.53 33.4 0 bottom
R290  0  [0603R]  54.74 32.13 180 bottom
R291  100K  [0603R]  36.32 29.97 270 bottom
R292  10K  [0603R]  20.07 21.72 180 bottom
R293  100  [0603R]  22.35 21.08 90 bottom
R294  36K  [0603R]  20.07 20.45 0 bottom
R295  [N_A]  [0603R]  153.29 152.27 0 bottom
R296  [N_A]  [0603R]  148.97 152.27 0 bottom
RV1  3386P-103(10K)  [3386P]  34.54 8.13 180 top
SB1  Open  [SB_0603]  70.48 159.77 90 top
SB2  Open  [SB_0603]  64.14 159.64 90 top
SB3  Closed  [SB_0603]  89.66 148.59 270 top
SB4  Closed  [SB_0603]  91.19 148.59 270 top
SB5  Closed  [SB_0603]  92.71 148.59 270 top
SB6  Closed  [SB_0603]  94.23 145.21 180 top
SB7  Closed  [SB_0603]  94.26 143.69 180 top
SB8  Closed  [SB_0603]  94.23 142.01 0 top
SB9  Closed  [SB_0603]  90.3 140.72 180 top
SB10  Closed  [SB_0603]  94.23 140.36 180 top
SB11  Closed  [SB_0603]  94.23 138.71 180 top
SB12  Open  [SB_0603]  90.3 135.25 0 top
SB13  Closed  [SB_0603]  11.43 114.81 270 top
SB14  Open  [SB_0603]  14.73 114.81 90 top
SB15  Open  [SB_0603]  17.65 109.6 90 top
SB16  Closed  [SB_0603]  20.57 109.6 90 top
SB17  Closed  [SB_0603]  129.54 103.89 270 top
SB18  Closed  [SB_0603]  128.02 100.84 90 top
SB19  Closed  [SB_0603]  129.54 100.84 90 top
SB24  Open  [SB_0603]  34.42 59.56 0 top
SB25  Closed  [SB_0603]  120.14 15.62 270 bottom
SB26  Closed  [SB_0603]  129.41 15.75 90 bottom
SB27  Open  [SB_0603]  94.89 156.16 180 bottom
SB28  Open  [SB_0603]  46.86 155.7 180 bottom
SB29  Closed  [SB_0603]  46.86 153.92 180 bottom
SB30  Open  [SB_0603]  41.27 153.67 180 bottom
SB31  Closed  [SB_0603]  46.86 152.27 0 bottom
SB32  Closed  [SB_0603]  41.27 152.15 180 bottom
SB33  Open  [SB_0603]  46.86 150.75 180 bottom
SB34  Closed  [SB_0603]  41.27 150.62 180 bottom
SB35  Open  [SB_0603]  83.95 149.48 90 bottom
SB36  Open  [SB_0603]  80.26 149.48 90 bottom
SB37  Open  [SB_0603]  76.96 149.48 90 bottom
SB38  Open  [SB_0603]  73.79 149.48 90 bottom
SB39  Closed  [SB_0603]  46.86 149.22 180 bottom
SB40  Closed  [SB_0603]  41.27 149.07 0 bottom
SB41  Open  [SB_0603]  46.86 147.57 0 bottom
SB42  Open  [SB_0603]  41.27 147.55 0 bottom
SB43  Open  [SB_0603]  46.86 146.05 180 bottom
SB44  Closed  [SB_0603]  41.27 145.92 0 bottom
SB45  Closed  [SB_0603]  46.86 144.53 180 bottom
SB46  Open  [SB_0603]  41.27 144.4 0 bottom
SB47  Closed  [SB_0603]  46.86 143 180 bottom
SB48  Open  [SB_0603]  41.27 142.88 0 bottom
SB49  Open  [SB_0603]  41.4 141.35 0 bottom
SB50  Closed  [SB_0603]  46.86 141.22 0 bottom
SB51  Open  [SB_0603]  46.86 139.7 0 bottom
SB52  Open  [SB_0603]  41.4 139.06 180 bottom
SB53  Closed  [SB_0603]  38.23 139.06 180 bottom
SB54  Closed  [SB_0603]  46.86 138.18 0 bottom
SB55  Closed  [SB_0603]  115.57 137.44 0 bottom
SB56  Closed  [SB_0603]  41.4 137.41 0 bottom
SB57  Open  [SB_0603]  38.23 137.41 180 bottom
SB58  Open  [SB_0603]  109.98 137.29 180 bottom
SB59  Open  [SB_0603]  46.86 136.65 0 bottom
SB60  Open  [SB_0603]  109.98 135.76 180 bottom
SB61  Open  [SB_0603]  41.27 135.76 180 bottom
SB62  Closed  [SB_0603]  38.23 135.76 0 bottom
SB63  Open  [SB_0603]  63.88 135.51 180 bottom
SB64  Open  [SB_0603]  41.27 133.86 180 bottom
SB65  Closed  [SB_0603]  38.23 133.86 0 bottom
SB66  Open  [SB_0603]  115.32 133.22 180 bottom
SB67  Closed  [SB_0603]  115.32 131.7 180 bottom
SB68  Open  [SB_0603]  109.98 130.81 0 bottom
SB69  Open  [SB_0603]  46.86 130.56 0 bottom
SB70  Open  [SB_0603]  41.4 130.43 0 bottom
SB71  Closed  [SB_0603]  115.32 130.18 180 bottom
SB72  Closed  [SB_0603]  109.98 129.29 0 bottom
SB73  Closed  [SB_0603]  46.86 129.03 0 bottom
SB74  Closed  [SB_0603]  41.4 128.91 0 bottom
SB75  Open  [SB_0603]  115.32 127 180 bottom
SB76  Open  [SB_0603]  46.86 125.86 0 bottom
SB77  Closed  [SB_0603]  115.32 125.48 180 bottom
SB78  Open  [SB_0603]  109.98 125.48 0 bottom
SB79  Closed  [SB_0603]  46.86 124.33 0 bottom
SB80  Open  [SB_0603]  115.32 123.95 180 bottom
SB81  Closed  [SB_0603]  109.98 123.95 0 bottom
SB82  Open  [SB_0603]  115.32 122.43 0 bottom
SB83  Closed  [SB_0603]  109.98 119.63 0 bottom
SB84  Open  [SB_0603]  37.59 29.97 90 bottom
SW1  09.03290.01  [SW1_3TH_2R54_10X2R5]  48.26 167.64 0 top
SW2  09.03290.01  [SW1_3TH_2R54_10X2R5]  48.26 163.96 0 top
T1  9012  [SOT-23]  18.29 101.35 0 top
T2  9013  [SOT-23]  12.7 83.82 270 top
T4  9013  [SOT-23]  19.94 20.57 180 top
T5  BSN20  [SOT-23]  153.16 154.81 270 bottom
T6  BSN20  [SOT-23]  149.22 154.69 270 bottom
T7  9013  [SOT-23]  10.16 110.74 270 bottom
T8  9013  [SOT-23]  12.7 103.12 0 bottom
TP1  1V8  [TP]  134.59 149.35 90 top
TP2  Ground  [TP]  143.76 169.93 0 top
TP3  Ground  [TP]  40.13 159.89 0 top
TP4  +3V3  [TP]  33.91 155.45 90 top
TP5  2V8  [TP]  127.25 155.45 90 top
TP6  VREF  [TP]  68.2 150.37 180 top
TP7  mco1  [TP]  154.94 144.53 0 top
TP8  mco1  [TP]  154.94 141.6 0 top
TP9  VDDA  [TP]  66.55 141.1 180 top
TP10  mco1  [TP]  154.94 139.06 0 top
TP11  mco1  [TP]  154.94 136.4 0 top
TP12  25MHz  [TP]  135.38 113.92 0 top
TP13  Ground  [TP]  36.09 94.49 0 top
TP14  5V  [TP]  12.7 65.02 0 top
TP15  mco1  [TP]  64.01 27.94 90 top
TP16  Ground  [TP]  102.23 4.06 0 top
U1  TFDU6300  [IR_VISHAY3]  136.27 169.93 0 top
U2  LD1117STR  [SOT-223]  132.84 155.96 180 top
U3  MT25QL512ABA8ESF-0SIT  [SOIC16W_1R27_10R3X10R33]  30.48 148.34 90 top
U4  STM32F4  [BGA216_0R8_13X13_SKT]  78.41 137.29 270 top
U5  ST3241EBPR  [SSOP28_0R65_10R2X7R8]  31.5 129.54 270 top
U6  DP83848CVV  [LQFP48_0R5_9X9]  128.02 121.79 0 top
U7  STMPS2151STR  [SOT23-5]  18.29 113.54 270 top
U8  USB3300-EZK  [QFN32_0R5_5X5]  28.45 106.05 0 top
U9  PC28F128M29EWLA  [FBGA64_1_11X13]  78.41 102.87 270 top
U10  ESDALC6V1W5  [SOT-353]  125.09 100.71 90 top
U11  STMPS2151STR  [SOT23-5]  10.67 94.49 0 top
U13  ESDALC6V1W5  [SOT-353]  145.29 83.06 0 top
U14  ESDALC6V1W5  [SOT-353]  145.29 76.2 180 top
U15  IS42S32800G-6BLI  [FBGA90_0R8_8X13]  91.06 74.17 270 top
U16  IS61WV102416BLL-10MLI  [BGA48_0R75_9X11]  66.04 73.66 270 top
U17  LD3985M33R  [SOT23-5]  27.05 68.83 90 top
U18  ST890CDR  [SOIC8_1R27_4R9X6]  35.59 53.21 0 top
U19  LD1086D2M33  [TO263-3]  49.15 53.85 180 top
U20  LD1117S18TR  [SOT-223]  109.86 43.31 180 top
U21  STM32F103CBT6  [LQFP48_0R5_9X9]  37.97 33.66 90 top
U22  STM32L152CCT6  [LQFP48_0R5_9X9]  56.26 33.66 90 top
U23  WM8994ECS_R  [BGA72_0R5_4R5X4]  118.11 29.08 90 top
U24  SN65HVD230  [SOIC8_1R27_4R9X6]  132.84 23.62 270 top
U25  -  [MP34DT01TR]  124.71 15.24 270 top
U26  -  [MP34DT01TR]  4.7 8.26 270 top
X1  25MHz(with socket)  [XTAL_SOCKET]  72.26 154.56 180 top
X2  NX3215SA-32.768KHZ-EXS00A-MU00525  [XTAL_2SM_3R2X1R5]  82.93 154.31 0 top
X3  SM7745HEX-24.0M[N_A]  [OSC_4SM_7X5]  141.6 147.07 0 top
X4  25MHz (with socket)  [XTAL_SOCKET]  140.72 125.22 90 top
X5  24MHz  [XTAL1]  26.04 115.32 180 top
X6  8MHz(12pF)  [XTAL_2SM_12R7X4R7]  37.34 22.23 180 top
Z1  SMAJ5.0A-TR  [SMA]  21.34 51.31 0 top

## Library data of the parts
B1-B3 = PB10
B4 = SW-JOY
BT1 = BAT_2SM_CR1220
C1 C2 C11 C15 C25 C27 C29 C34-C36 C38 C41-C47 C52 C55 C56 C59 C62-C64 C73 C80 C81 C87 C88 C90 C93 C94 C100 C102 C104-C106 C122 C123 C137-C139 C142 C145 C146 C148-C154 C156-C173 C175 C178 C180 C181 C183 = 0603C: signal model: DEFAULT_CAPACITOR_100000pF_1_2
C3 C4 C37 C48 C49 C65 C109 C115 C147 = TAN-A: signal model: DEFAULT_CAPACITOR_4.7e+06pF_1_2
C5 C19 C61 C66 C67 C144 C155 = TAN-A: signal model: DEFAULT_CAPACITOR_1e+07pF_1_2
C6-C10 C12-C14 C18 C24 C26 C28 C53 C54 C57 C103 C107 C130 = 0603C
C16 = 0603C: signal model: DEFAULT_CAPACITOR_1000pF_1_2
C17 C95-C99 = 0603C: signal model: DEFAULT_CAPACITOR_10000pF_1_2
C20 C23 C84 C85 = 0603C: signal model: DEFAULT_CAPACITOR_20pF_1_2
C21 C22 = 0603C: signal model: DEFAULT_CAPACITOR_10pF_1_2
C30 C33 = 0603C: signal model: DEFAULT_CAPACITOR_22pF_1_2
C31 C32 C143 = 1206C: signal model: DEFAULT_CAPACITOR_2.2e+06pF_2_1
C39 C40 = 0603C: signal model: DEFAULT_CAPACITOR_33pF_1_2
C58 = CAE_5R3X5R3_H5R4: signal model: DEFAULT_CAPACITOR_4.7e+07pF_2_1
C60 = C310M-6: signal model: DEFAULT_CAPACITOR_2.2e+08pF_1_2
C68 C70 C71 C76 C78 C89 C92 C101 = 0603C: signal model: DEFAULT_CAPACITOR_4.7e+06pF_1_2
C69 C72 C74 C91 = 0603C: signal model: DEFAULT_CAPACITOR_1e+06pF_1_2
C75 C77 C79 = 0603C: signal model: DEFAULT_CAPACITOR_2.2e+06pF_1_2
C82 C110-C113 C116-C121 C124-C129 C131-C133 C135 C136 C141 C174 C176 C177 C179 C182 = 0402C: signal model: DEFAULT_CAPACITOR_100000pF_1_2
C83 C134 C140 = 0402C
C86 C108 C114 = TAN-A: signal model: DEFAULT_CAPACITOR_1e+06pF_1_2
CN1 = IDC34S
CN2 = SSM-104-L-DH
CN3 CN24 JP1 JP2 JP4 JP9 JP11 JP13 JP20 JP21 = SIP2
CN4 = CLM-120-02-L-D
CN5 CN6 = FTR-130-53-L-D-LC
CN7 CN23 = DB9_M
CN8 CN13 CN14 = MOLEX_47590001
CN9 = RJ45_J0011D01BNL
CN10 CN11 = FTR-120-53-L-D-LC
CN12 = FTSH-110-01-L-DV
CN15 = QSH-030-01-F-D-A
CN16 = IDC20S
CN17 = MSD_PJS008_
CN18 = FTSH-125-01-F-DV
CN19 = PWR_JACK_DC10
CN20 CN21 = HDR_2X3-1_2R54-6
CN22 = USB-B
CN25 CN28 = COUPON
CN26 CN27 = PJ3028B
D1 D2 D7-D12 D15 D16 = SOD-323
D3 = BGA4_0R4_0R8X0R8
D4 = BGA4_0R4_1X1
D5 D6 = BGA11_0R5_1R57X2R07
D13 = TYCO_ZEN056V130A24LS
D14 T1 T2 T4-T8 = SOT-23
H1-H4 = HOLE_C9D4R5
JP3 JP5-JP8 JP10 JP12 JP15-JP19 = SIP3
JP14 = HDR_2X6_2R54
L1-L4 L6-L9 = 0603L
L5 = BNX001
LD1-LD11 = 0603D
LD12 = LED2_3528
R1 R29 = 0603R: signal model: DEFAULT_RESISTOR_47OHM_1_2
R2 = 0603R: signal model: DEFAULT_RESISTOR_5.1OHM_1_2
R3 R6 R21 R68 R79 R84 R86 R88 R106 R116 R125 R133 R134 R136 R137 R143 R167 R171 R173 R185 R186 R197-R201 R218 R239 R253 R282 R292 = 0603R: signal model: DEFAULT_RESISTOR_10000OHM_1_2
R4 R5 R8-R12 R15 R17-R20 R28 R30 R31 R33 R67 R81 R82 R85 R94 R98 R99 R101 R107 R109 R111 R115 R117 R119 R135 R141 R142 R153 R154 R163 R172 R176 R177 R179-R181 R190 R203 R210 R211 R214 R252 R272 R278 R280 R281 R285 R287 R288 R290 = 0603R: signal model: DEFAULT_RESISTOR_0.001OHM_1_2
R7 = 0603R: signal model: DEFAULT_RESISTOR_150OHM_1_2
R13 R144 R157 R289 R291 = 0603R: signal model: DEFAULT_RESISTOR_100000OHM_1_2
R14 R112 = 0603R: signal model: DEFAULT_RESISTOR_3300OHM_1_2
R16 R175 = 0603R: signal model: DEFAULT_RESISTOR_120OHM_1_2
R22 R97 R102 R104 R114 R123 R124 R127-R129 R131 R132 R174 R178 R255 = 0603R: signal model: 0603R_[n/a]
R23 R25 R27 R40 R222 R237 = 0402R: signal model: DEFAULT_RESISTOR_33OHM_1_2
R24 R39 R206 R229 R231 R234 = 0603R: signal model: DEFAULT_RESISTOR_220000OHM_1_2
R26 R147 R158 R215 = 0402R: signal model: DEFAULT_RESISTOR_10000OHM_1_2
R32 R34 R35 R37 R38 R41 R48-R56 R58-R66 R221 R223 R226 R230 R232 R236 R240 R241 R243-R251 R256-R271 R273-R276 = 0402R: signal model: 0402R_33
R36 = 0603R: signal model: 0603R_33
R42-R47 R57 R113 R216 R217 R227 R228 R233 R235 R238 R242 R277 = 0603R: signal model: DEFAULT_RESISTOR_33OHM_1_2
R69 R151 R152 R182 = 0603R: signal model: DEFAULT_RESISTOR_1500OHM_1_2
R70 R71 R73 R75 R76 R160 = 0603R: signal model: DEFAULT_RESISTOR_2200OHM_1_2
R72 R118 = 0603R: signal model: DEFAULT_RESISTOR_240OHM_1_2
R74 R91 R155 R159 R168 R212 R220 R225 R286 R295 R296 = 0603R
R77 = 0603R: signal model: DEFAULT_RESISTOR_4870OHM_1_2
R78 R100 R121 R126 R145 R146 R148-R150 = 0603R: signal model: DEFAULT_RESISTOR_47000OHM_1_2
R80 R87 R92 R93 R96 R103 R283 R284 = 0603R: signal model: DEFAULT_RESISTOR_22OHM_1_2
R83 R90 R105 R110 = 0603R: signal model: DEFAULT_RESISTOR_50OHM_1_2
R89 R108 R122 R205 = 0603R: signal model: DEFAULT_RESISTOR_330OHM_1_2
R95 R130 R213 = 0603R: signal model: DEFAULT_RESISTOR_820OHM_1_2
R120 R279 = 0603R: signal model: DEFAULT_RESISTOR_620OHM_1_2
R140 = 0402R: signal model: DEFAULT_RESISTOR_2400OHM_1_2
R156 = 0402R: signal model: DEFAULT_RESISTOR_510OHM_1_2
R161 R162 = 0603R: signal model: DEFAULT_RESISTOR_20OHM_1_2
R164 R165 = 0402R
R169 R170 R195 R204 R219 R224 = 0603R: signal model: DEFAULT_RESISTOR_4700OHM_1_2
R183 R209 = 0402R: signal model: DEFAULT_RESISTOR_180OHM_1_2
R184 R208 = 0402R: signal model: DEFAULT_RESISTOR_1000OHM_1_2
R187 = 0603R: signal model: DEFAULT_RESISTOR_1000OHM_1_2
R188 R189 R202 R207 R293 = 0603R: signal model: DEFAULT_RESISTOR_100OHM_1_2
R191-R193 = 0603R: signal model: DEFAULT_RESISTOR_680OHM_1_2
R194 = 0603R: signal model: DEFAULT_RESISTOR_510OHM_1_2
R196 = 0603R: signal model: DEFAULT_RESISTOR_2700OHM_1_2
R254 = 0603R: signal model: 0603R_33[N_A]
R294 = 0603R: signal model: DEFAULT_RESISTOR_36000OHM_1_2
RV1 = 3386P
SB1 SB2 SB12 SB14 SB15 SB24 SB28 SB30 SB33 SB35-SB38 SB41-SB43 SB46 SB48 SB49 SB51 SB52 SB57-SB61 SB63 SB64 SB66 SB68-SB70 SB75 SB76 SB78 SB80 SB82 SB84 = SB_0603
SB3-SB11 SB13 SB16-SB19 SB25 SB26 SB29 SB31 SB32 SB34 SB39 SB40 SB44 SB45 SB47 SB50 SB53-SB56 SB62 SB65 SB67 SB71-SB74 SB77 SB79 SB81 SB83 = SB_0603: signal model: SB_0603_Closed
SB27 = SB_0603: signal model: SB_0603_Open
SW1 SW2 = SW1_3TH_2R54_10X2R5
TP1-TP16 = TP
U1 = IR_VISHAY3
U2 U20 = SOT-223
U3 = SOIC16W_1R27_10R3X10R33
U4 = BGA216_0R8_13X13_SKT
U5 = SSOP28_0R65_10R2X7R8
U6 U21 U22 = LQFP48_0R5_9X9
U7 U11 U17 = SOT23-5
U8 = QFN32_0R5_5X5
U9 = FBGA64_1_11X13
U10 U13 U14 = SOT-353
U15 = FBGA90_0R8_8X13
U16 = BGA48_0R75_9X11
U18 U24 = SOIC8_1R27_4R9X6
U19 = TO263-3
U23 = BGA72_0R5_4R5X4
U25 U26 = MP34DT01TR
X1 X4 = XTAL_SOCKET
X2 = XTAL_2SM_3R2X1R5
X3 = OSC_4SM_7X5
X5 = XTAL1
X6 = XTAL_2SM_12R7X4R7
Z1 = SMA

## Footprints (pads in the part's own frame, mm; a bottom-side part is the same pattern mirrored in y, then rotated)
0402C
  rect 0.559x0.559 smd: 1(-0.508,0) 2(0.508,0)
0402R
  rect 0.559x0.559 smd: 1(-0.508,0) 2(0.508,0)
0603C
  rect 0.889x0.813 smd: 1(-0.762,0) 2(0.762,0)
0603D
  rect 0.889x0.813 smd: 1(-0.762,0) 2(0.762,0)
0603L
  rect 0.889x0.813 smd: 1(-0.762,0) 2(0.762,0)
0603R
  rect 0.787x0.813 smd: 1(-0.762,0) 2(0.762,0)
1206C
  rect 1.168x1.524 smd: 1(-1.473,0) 2(1.473,0)
3386P
  rect 1.168x1.168 hole 0.762: 1(-2.54,0)
  round 1.168 hole 0.762: 2(0,2.54) 3(2.54,0)
BAT_2SM_CR1220
  round 1.473 hole 1.473 unplated: (-3.75,0)
  round 1.194 hole 1.194 unplated: (3.75,0)
  rect 4.064x2.159 smd: 1(-7.95,0) 2(7.95,0)
BGA4_0R4_0R8X0R8
  round 0.203 smd: A1(-0.2,0.2) A2(0.2,0.2) B1(-0.2,-0.2) B2(0.2,-0.2)
BGA4_0R4_1X1
  round 0.203 smd: A1(-0.2,0.2) A2(0.2,0.2) B1(-0.2,-0.2) B2(0.2,-0.2)
BGA11_0R5_1R57X2R07
  round 0.249 smd: A2(0,0.75) A3(0.5,0.75) B1(-0.5,0.25) B2(0,0.25) B3(0.5,0.25) C1(-0.5,-0.25) C2(0,-0.25) C3(0.5,-0.25) D1(-0.5,-0.75) D2(0,-0.75) D3(0.5,-0.75)
BGA48_0R75_9X11
  round 0.356 smd: A1(-1.875,2.625) A2(-1.125,2.625) A3(-0.375,2.625) A4(0.375,2.625) A5(1.125,2.625) A6(1.875,2.625) B1(-1.875,1.875) B2(-1.125,1.875) B3(-0.375,1.875) B4(0.375,1.875) B5(1.125,1.875) B6(1.875,1.875) C1(-1.875,1.125) C2(-1.125,1.125) C3(-0.375,1.125) C4(0.375,1.125) C5(1.125,1.125) C6(1.875,1.125) D1(-1.875,0.375) D2(-1.125,0.375) D3(-0.375,0.375) D4(0.375,0.375) D5(1.125,0.375) D6(1.875,0.375) E1(-1.875,-0.375) E2(-1.125,-0.375) E3(-0.375,-0.375) E4(0.375,-0.375) E5(1.125,-0.375) E6(1.875,-0.375) F1(-1.875,-1.125) F2(-1.125,-1.125) F3(-0.375,-1.125) F4(0.375,-1.125) F5(1.125,-1.125) F6(1.875,-1.125) G1(-1.875,-1.875) G2(-1.125,-1.875) G3(-0.375,-1.875) G4(0.375,-1.875) G5(1.125,-1.875) G6(1.875,-1.875) H1(-1.875,-2.625) H2(-1.125,-2.625) H3(-0.375,-2.625) H4(0.375,-2.625) H5(1.125,-2.625) H6(1.875,-2.625)
BGA72_0R5_4R5X4
  round 0.249 smd: A1(-2,1.75) A2(-1.5,1.75) A3(-1,1.75) A4(-0.5,1.75) A5(0,1.75) A6(0.5,1.75) A7(1,1.75) A8(1.5,1.75) A9(2,1.75) B1(-2,1.25) B2(-1.5,1.25) B3(-1,1.25) B4(-0.5,1.25) B5(0,1.25) B6(0.5,1.25) B7(1,1.25) B8(1.5,1.25) B9(2,1.25) C1(-2,0.75) C2(-1.5,0.75) C3(-1,0.75) C4(-0.5,0.75) C5(0,0.75) C6(0.5,0.75) C7(1,0.75) C8(1.5,0.75) C9(2,0.75) D1(-2,0.25) D2(-1.5,0.25) D3(-1,0.25) D4(-0.5,0.25) D5(0,0.25) D6(0.5,0.25) D7(1,0.25) D8(1.5,0.25) D9(2,0.25) E1(-2,-0.25) E2(-1.5,-0.25) E3(-1,-0.25) E4(-0.5,-0.25) E5(0,-0.25) E6(0.5,-0.25) E7(1,-0.25) E8(1.5,-0.25) E9(2,-0.25) F1(-2,-0.75) F2(-1.5,-0.75) F3(-1,-0.75) F4(-0.5,-0.75) F5(0,-0.75) F6(0.5,-0.75) F7(1,-0.75) F8(1.5,-0.75) F9(2,-0.75) G1(-2,-1.25) G2(-1.5,-1.25) G3(-1,-1.25) G4(-0.5,-1.25) G5(0,-1.25) G6(0.5,-1.25) G7(1,-1.25) G8(1.5,-1.25) G9(2,-1.25) H1(-2,-1.75) H2(-1.5,-1.75) H3(-1,-1.75) H4(-0.5,-1.75) H5(0,-1.75) H6(0.5,-1.75) H7(1,-1.75) H8(1.5,-1.75) H9(2,-1.75)
BGA216_0R8_13X13_SKT
  round 1.702 hole 1.702 unplated: (-8.237,7.863) (-8.237,-7.863) (7.487,7.863) (7.487,-7.863)
  round 0.85 hole 0.85 unplated: (-8.237,-2.783) (7.487,5.323)
  round 0.406 smd: A1(-5.6,5.6) A2(-4.8,5.6) A3(-4,5.6) A4(-3.2,5.6) A5(-2.4,5.6) A6(-1.6,5.6) A7(-0.8,5.6) A8(0,5.6) A9(0.8,5.6) A10(1.6,5.6) A11(2.4,5.6) A12(3.2,5.6) A13(4,5.6) A14(4.8,5.6) A15(5.6,5.6) B1(-5.6,4.8) B2(-4.8,4.8) B3(-4,4.8) B4(-3.2,4.8) B5(-2.4,4.8) B6(-1.6,4.8) B7(-0.8,4.8) B8(0,4.8) B9(0.8,4.8) B10(1.6,4.8) B11(2.4,4.8) B12(3.2,4.8) B13(4,4.8) B14(4.8,4.8) B15(5.6,4.8) C1(-5.6,4) C2(-4.8,4) C3(-4,4) C4(-3.2,4) C5(-2.4,4) C6(-1.6,4) C7(-0.8,4) C8(0,4) C9(0.8,4) C10(1.6,4) C11(2.4,4) C12(3.2,4) C13(4,4) C14(4.8,4) C15(5.6,4) D1(-5.6,3.2) D2(-4.8,3.2) D3(-4,3.2) D4(-3.2,3.2) D5(-2.4,3.2) D6(-1.6,3.2) D7(-0.8,3.2) D8(0,3.2) D9(0.8,3.2) D10(1.6,3.2) D11(2.4,3.2) D12(3.2,3.2) D13(4,3.2) D14(4.8,3.2) D15(5.6,3.2) E1(-5.6,2.4) E2(-4.8,2.4) E3(-4,2.4) E4(-3.2,2.4) E5(-2.4,2.4) E6(-1.6,2.4) E7(-0.8,2.4) E8(0,2.4) E9(0.8,2.4) E10(1.6,2.4) E11(2.4,2.4) E12(3.2,2.4) E13(4,2.4) E14(4.8,2.4) E15(5.6,2.4) F1(-5.6,1.6) F2(-4.8,1.6) F3(-4,1.6) F4(-3.2,1.6) F5(-2.4,1.6) F6(-1.6,1.6) F7(-0.8,1.6) F8(0,1.6) F9(0.8,1.6) F10(1.6,1.6) F11(2.4,1.6) F12(3.2,1.6) F13(4,1.6) F14(4.8,1.6) F15(5.6,1.6) G1(-5.6,0.8) G2(-4.8,0.8) G3(-4,0.8) G4(-3.2,0.8) G5(-2.4,0.8) G6(-1.6,0.8) G10(1.6,0.8) G11(2.4,0.8) G12(3.2,0.8) G13(4,0.8) G14(4.8,0.8) G15(5.6,0.8) H1(-5.6,0) H2(-4.8,0) H3(-4,0) H4(-3.2,0) H5(-2.4,0) H6(-1.6,0) H10(1.6,0) H11(2.4,0) H12(3.2,0) H13(4,0) H14(4.8,0) H15(5.6,0) J1(-5.6,-0.8) J2(-4.8,-0.8) J3(-4,-0.8) J4(-3.2,-0.8) J5(-2.4,-0.8) J6(-1.6,-0.8) J10(1.6,-0.8) J11(2.4,-0.8) J12(3.2,-0.8) J13(4,-0.8) J14(4.8,-0.8) J15(5.6,-0.8) K1(-5.6,-1.6) K2(-4.8,-1.6) K3(-4,-1.6) K4(-3.2,-1.6) K5(-2.4,-1.6) K6(-1.6,-1.6) K7(-0.8,-1.6) K8(0,-1.6) K9(0.8,-1.6) K10(1.6,-1.6) K11(2.4,-1.6) K12(3.2,-1.6) K13(4,-1.6) K14(4.8,-1.6) K15(5.6,-1.6) L1(-5.6,-2.4) L2(-4.8,-2.4) L3(-4,-2.4) L4(-3.2,-2.4) L5(-2.4,-2.4) L6(-1.6,-2.4) L7(-0.8,-2.4) L8(0,-2.4) L9(0.8,-2.4) L10(1.6,-2.4) L11(2.4,-2.4) L12(3.2,-2.4) L13(4,-2.4) L14(4.8,-2.4) L15(5.6,-2.4) M1(-5.6,-3.2) M2(-4.8,-3.2) M3(-4,-3.2) M4(-3.2,-3.2) M5(-2.4,-3.2) M6(-1.6,-3.2) M7(-0.8,-3.2) M8(0,-3.2) M9(0.8,-3.2) M10(1.6,-3.2) M11(2.4,-3.2) M12(3.2,-3.2) M13(4,-3.2) M14(4.8,-3.2) M15(5.6,-3.2) N1(-5.6,-4) N2(-4.8,-4) N3(-4,-4) N4(-3.2,-4) N5(-2.4,-4) N6(-1.6,-4) N7(-0.8,-4) N8(0,-4) N9(0.8,-4) N10(1.6,-4) N11(2.4,-4) N12(3.2,-4) N13(4,-4) N14(4.8,-4) N15(5.6,-4) P1(-5.6,-4.8) P2(-4.8,-4.8) P3(-4,-4.8) P4(-3.2,-4.8) P5(-2.4,-4.8) P6(-1.6,-4.8) P7(-0.8,-4.8) P8(0,-4.8) P9(0.8,-4.8) P10(1.6,-4.8) P11(2.4,-4.8) P12(3.2,-4.8) P13(4,-4.8) P14(4.8,-4.8) P15(5.6,-4.8) R1(-5.6,-5.6) R2(-4.8,-5.6) R3(-4,-5.6) R4(-3.2,-5.6) R5(-2.4,-5.6) R6(-1.6,-5.6) R7(-0.8,-5.6) R8(0,-5.6) R9(0.8,-5.6) R10(1.6,-5.6) R11(2.4,-5.6) R12(3.2,-5.6) R13(4,-5.6) R14(4.8,-5.6) R15(5.6,-5.6)
